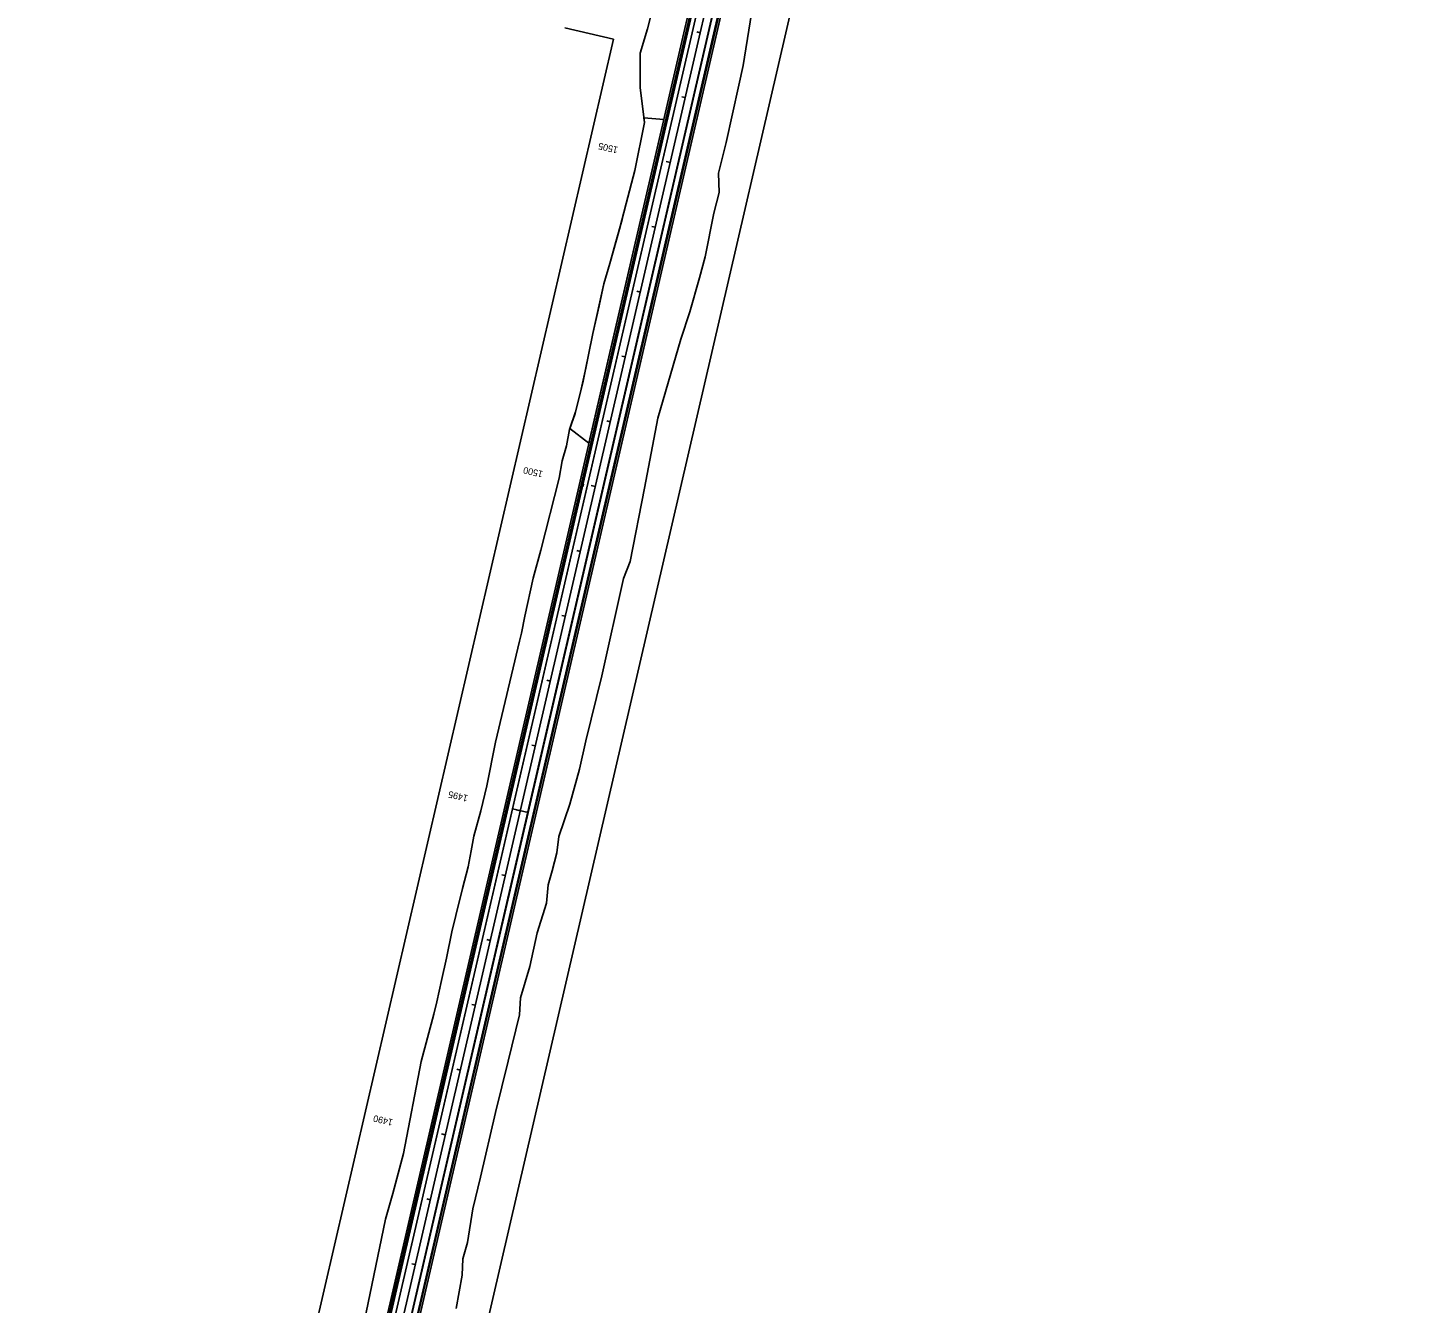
# Model space of a CAD drawing. Extents: x 21596487 to 21601936, y 8263704 to 8275922.
# Drawn here: x 21596607 to 21598711, y 8269134 to 8271050 of the extents above; entities that cross this region are included whole.
import ezdxf

# ---------------------------------------------------------------- set-up
doc = ezdxf.new("R2010")
doc.units = 0
for name, color, linetype in [('Default', 7, 'Continuous'), ('dsnGroundLineIntercept', 7, 'Continuous'), ('dsnPaintPlaceBrokenCenterLineYellow', 7, 'Continuous'), ('dsnPaintPlaceDottedLineYellow', 7, 'Continuous'), ('dsnXsROWLabelLineExist', 7, 'Continuous'), ('EdgePaved', 7, 'Continuous'), ('EdgeUnpaved', 7, 'Continuous'), ('ErosionControl', 7, 'Continuous'), ('Hatch', 7, 'Continuous'), ('Joints', 7, 'Continuous'), ('TC_DNC', 7, 'Continuous'), ('TC_GranularBackFill', 7, 'Continuous'), ('TC_MacadamStone', 7, 'Continuous'), ('TC_SpecialBackfill', 7, 'Continuous'), ('Wall', 7, 'Continuous')]:
    doc.layers.add(name, color=color, linetype=linetype)

msp = doc.modelspace()

# ---------------------------------------------------------------- linework, layer by layer
at = {"layer": 'Default'}
msp.add_line((21596728.7, 8267202.6), (21598588.8, 8275242.6), dxfattribs=at)
msp.add_line((21596728.7, 8267202.6), (21598588.8, 8275242.6), dxfattribs=at)
at = {"layer": 'dsnGroundLineIntercept'}
for points in [[(21597571.1, 8271182.5), (21597538, 8271048.7), (21597526.7, 8271011.7), (21597526.6, 8270960.5), (21597533.4, 8270907.8), (21597518.5, 8270835.5), (21597505.6, 8270786.1), (21597499.5, 8270761.9), (21597490.4, 8270728.3), (21597486.3, 8270713.9), (21597481.1, 8270695.9), (21597472.4, 8270665.5), (21597465.2, 8270632.2), (21597455.7, 8270590.5), (21597440.9, 8270518.8), (21597434.9, 8270494.5), (21597428.9, 8270470.2), (21597420.5, 8270446.5), (21597415.9, 8270421.9), (21597409.7, 8270399.2), (21597405.3, 8270373.1), (21597377.5, 8270264.9), (21597365.8, 8270222.8), (21597353.7, 8270165.8), (21597348.6, 8270140.3), (21597345.4, 8270128.1), (21597309.2, 8269976.5), (21597296.5, 8269910.7), (21597287.5, 8269873.5), (21597276.7, 8269835.4), (21597273, 8269813.2), (21597268.1, 8269789), (21597259.9, 8269756.5), (21597250, 8269716.1), (21597243.7, 8269691.3), (21597235.8, 8269651.9), (21597228.4, 8269618.4), (21597221.3, 8269586.5), (21597216.6, 8269567.8), (21597197.7, 8269496.7), (21597171.4, 8269358.2), (21597154.9, 8269298.5), (21597144, 8269259.8), (21597112, 8269105)], [(21597250.4, 8269125.3), (21597259.5, 8269175.6), (21597260.1, 8269200.3), (21597267.2, 8269224.6), (21597275.1, 8269275), (21597286.9, 8269322.7), (21597309.4, 8269420.2), (21597328.2, 8269497), (21597345.3, 8269566.9), (21597346.9, 8269592.4), (21597361.1, 8269639.2), (21597372.2, 8269690.1), (21597386.2, 8269734.7), (21597388.3, 8269762.3), (21597394.7, 8269783.4), (21597401.7, 8269810.1), (21597404.6, 8269834.7), (21597421, 8269883.2), (21597435.7, 8269935.9), (21597445.3, 8269978.5), (21597469.4, 8270076.3), (21597501.8, 8270222.4), (21597511.7, 8270248.2), (21597533.4, 8270358.3), (21597553.2, 8270463.3), (21597588.1, 8270582.4), (21597601.6, 8270623.2), (21597615.8, 8270674.2), (21597624.6, 8270706.1), (21597637.4, 8270771.3), (21597645.4, 8270802.5), (21597644.3, 8270831.6), (21597656.2, 8270877.6), (21597675.1, 8270963.9), (21597681.7, 8270993.6), (21597702.8, 8271125.4)]]:
    msp.add_lwpolyline(points, dxfattribs=at)
at = {"layer": 'dsnPaintPlaceBrokenCenterLineYellow'}
msp.add_line((21597006.2, 8268402), (21598343, 8274180.5), dxfattribs=at)
at = {"layer": 'dsnPaintPlaceDottedLineYellow'}
for p, q in [((21596717, 8267205.3), (21598523, 8275011.8)), ((21596739.7, 8267200), (21598545.7, 8275006.6))]:
    msp.add_line(p, q, dxfattribs=at)
at = {"layer": 'dsnXsROWLabelLineExist'}
for p, q in [((21596850.5, 8267174.4), (21598710.5, 8275214.5)), ((21597486.5, 8271032.9), (21597413.5, 8271049.8)), ((21596606.9, 8267230.7), (21597486.5, 8271032.9))]:
    msp.add_line(p, q, dxfattribs=at)
at = {"layer": 'EdgePaved'}
msp.add_lwpolyline([(21597441.6, 8270364.1), (21597441, 8270361.2), (21597439, 8270361.6), (21597439.7, 8270364.5)], close=True, dxfattribs=at)
at = {"layer": 'EdgeUnpaved'}
for p, q in [((21596709.9, 8267206.9), (21598472.3, 8274824.9)), ((21596710.4, 8267206.8), (21598472.9, 8274825.4))]:
    msp.add_line(p, q, dxfattribs=at)
at = {"layer": 'ErosionControl'}
for p, q in [((21597617.1, 8271042.6), (21597611.7, 8271043.8)), ((21597594.5, 8270945.1), (21597589.2, 8270946.4)), ((21597572, 8270847.7), (21597566, 8270849.1)), ((21597549.5, 8270750.3), (21597544.1, 8270751.5)), ((21597526.9, 8270652.9), (21597521.6, 8270654.1)), ((21597504.4, 8270555.4), (21597499, 8270556.7)), ((21597481.9, 8270458), (21597476.5, 8270459.2)), ((21597459.3, 8270360.6), (21597453.3, 8270362)), ((21597436.8, 8270263.1), (21597431.4, 8270264.4)), ((21597414.2, 8270165.7), (21597408.9, 8270167)), ((21597391.7, 8270068.3), (21597386.3, 8270069.5)), ((21597369.2, 8269970.9), (21597363.8, 8269972.1)), ((21597346.6, 8269873.4), (21597340.6, 8269874.8)), ((21597324.1, 8269776), (21597318.7, 8269777.3)), ((21597301.5, 8269678.6), (21597296.2, 8269679.8)), ((21597279, 8269581.2), (21597273.6, 8269582.4)), ((21597256.5, 8269483.7), (21597251.1, 8269485)), ((21597233.9, 8269386.3), (21597228, 8269387.7)), ((21597211.4, 8269288.9), (21597206, 8269290.1)), ((21597188.8, 8269191.5), (21597183.5, 8269192.7))]:
    msp.add_line(p, q, dxfattribs=at)
at = {"layer": 'Hatch'}
msp.add_lwpolyline([(21597532.5, 8270914.8), (21597562.4, 8270912.5), (21597449.8, 8270425.9), (21597421.1, 8270448.1), (21597429.6, 8270472.9), (21597438, 8270507), (21597444.1, 8270534.3), (21597455.7, 8270590.5), (21597472.4, 8270665.5), (21597481.1, 8270695.9), (21597495.7, 8270747.7), (21597505.6, 8270786.1), (21597518.5, 8270835.5), (21597533.4, 8270907.8)], close=True, dxfattribs=at)
at = {"layer": 'TC_DNC'}
for p, q in [((21596708, 8267207.3), (21598514, 8275013.9)), ((21596749.4, 8267197.8), (21598555.4, 8275004.4))]:
    msp.add_line(p, q, dxfattribs=at)
at = {"layer": 'TC_GranularBackFill'}
msp.add_line((21596728.7, 8267202.6), (21598588.8, 8275242.6), dxfattribs=at)
at = {"layer": 'TC_MacadamStone'}
for p, q in [((21596709.2, 8267207.1), (21598515.3, 8275013.6)), ((21596748.2, 8267198.1), (21598554.2, 8275004.6))]:
    msp.add_line(p, q, dxfattribs=at)
at = {"layer": 'TC_SpecialBackfill'}
for p, q in [((21597673, 8271337.5), (21597334.9, 8269876.1)), ((21597358.3, 8269870.7), (21597696.4, 8271332.1)), ((21597334.9, 8269876.1), (21596996.8, 8268414.7)), ((21597020.2, 8268409.3), (21597358.3, 8269870.7)), ((21597358.3, 8269870.7), (21597334.9, 8269876.1)), ((21597334.9, 8269876.1), (21597358.3, 8269870.7))]:
    msp.add_line(p, q, dxfattribs=at)
at = {"layer": 'Wall'}
for p, q in [((21596705.3, 8267208), (21598511.4, 8275014.5)), ((21596752.1, 8267197.2), (21598558.1, 8275003.7))]:
    msp.add_line(p, q, dxfattribs=at)

# ---------------------------------------------------------------- texts
at = {"layer": 'Joints'}
for s, p in [('1505', (21597494.1, 8270870.9)), ('1500', (21597381.4, 8270383.7)), ('1495', (21597268.7, 8269896.6)), ('1490', (21597156, 8269409.5))]:
    msp.add_text(s, height=10, rotation=166.974, dxfattribs=at).set_placement(p)

doc.saveas('drawing.dxf')
